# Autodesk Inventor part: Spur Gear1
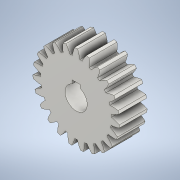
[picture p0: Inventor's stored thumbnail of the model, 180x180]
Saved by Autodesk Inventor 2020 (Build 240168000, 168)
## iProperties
Created: 2019-09
Part Number: Spur Gear1
Material: Steel
Document SubType Name: Modeling
Designer: user
Categories: <?xml version="1.0" encoding="UTF-16"?> <MemberInstance><Categories><FamilyTemplate><FamilyTemplateParameter ValueType="xs:double" Id="1" ObjectReferenceKey="da
Density: 1 g/cm^3
Appearance: Steel
CustomPartVersion: 1
Author: user
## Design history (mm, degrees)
sketch "Sketch1"
  geometry: C1 r 15.615 at (0, 0)
  constraints: 1 centre point
  dimensions: "d0" = 31.22933 diameter of C1 (= da_da)
extrude "Extrusion1" new body sketch "Sketch1" distance "d1" = 10 (= da_b); taper "d2" = 0 deg
workplane "Work Plane2"
sketch "Sketch2"
  geometry: C1 r 15.615 at (0, 0) reference; C2 r 14.457 at (0, 0)
  constraints: 1 centre point, 1 coincident
  dimensions: "d3" = 28.91429 diameter of C2 (= da_dw)
feature "Pitch Diameter" sketch "Sketch2" dims "d4" = 10, "d5" = 0
workplane "Work Plane8"
workplane "Work Plane9"
feature "Spur Gear" dims "d4" = 10, "da_b" = 10, "da_d" = 28.75, "da_aw" = 44, "da_da" = 31.22933, "da_df" = 25.625, "da_dw" = 28.91429, angle "da_beta" = 0 deg, "da_lefttooth" = 0, "da_righttooth" = 0
sketch "Sketch3"
  geometry: L1 (-1.432, 4.995)-(1.432, 4.995); L2 (1.432, 4.995)-(1.432, 3.735); L3 (-1.432, 3.735)-(-1.432, 4.995); A1 r 4 centre (0, 0) between (-1.432, 3.735) and (1.432, 3.735); 2 further points
  constraints: 6 end point, 2 point on circle, 1 centre point, 1 coincident, 1 horizontal, 1 midpoint, 1 parallel, 1 perpendicular, 1 vertical alignment
  dimensions: "d49" = 8 diameter of A1
extrude "Extrusion2" cut sketch "Sketch3" extent not by distance; stored distance "d50" = 0; taper "d51" = 0 deg
body "Solid1"
body "Srf1"
other parameters: "d16" = 44 (= da_aw), "d17" = 0, "d34" = 1.36591 (computed from da_z), "d39" = 0, "d41" = 0, "d43" = 44 (= da_aw), "d46" = 44 (= da_aw), "d47" = 0, "d48" = 0
